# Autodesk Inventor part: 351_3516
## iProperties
Author: tomm
Created: 2002-01
Part Number: 351_3516
Document SubType Name: Modeling
Designer: tomm
Material: Steel, Mild
Control State: 0
Master: False
Checked Out: False
Last Check In Date: 2002-01-29
PropertySet Name: Design Tracking Control
Last Check In By: tomm
Shininess: 70.0
PropertySet Name: _Private Model Information
Density: 7.86
Volume: 7.04332240919412
Area: 56.588186389056794
PropertySet Name: Model Information
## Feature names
1. Base1
